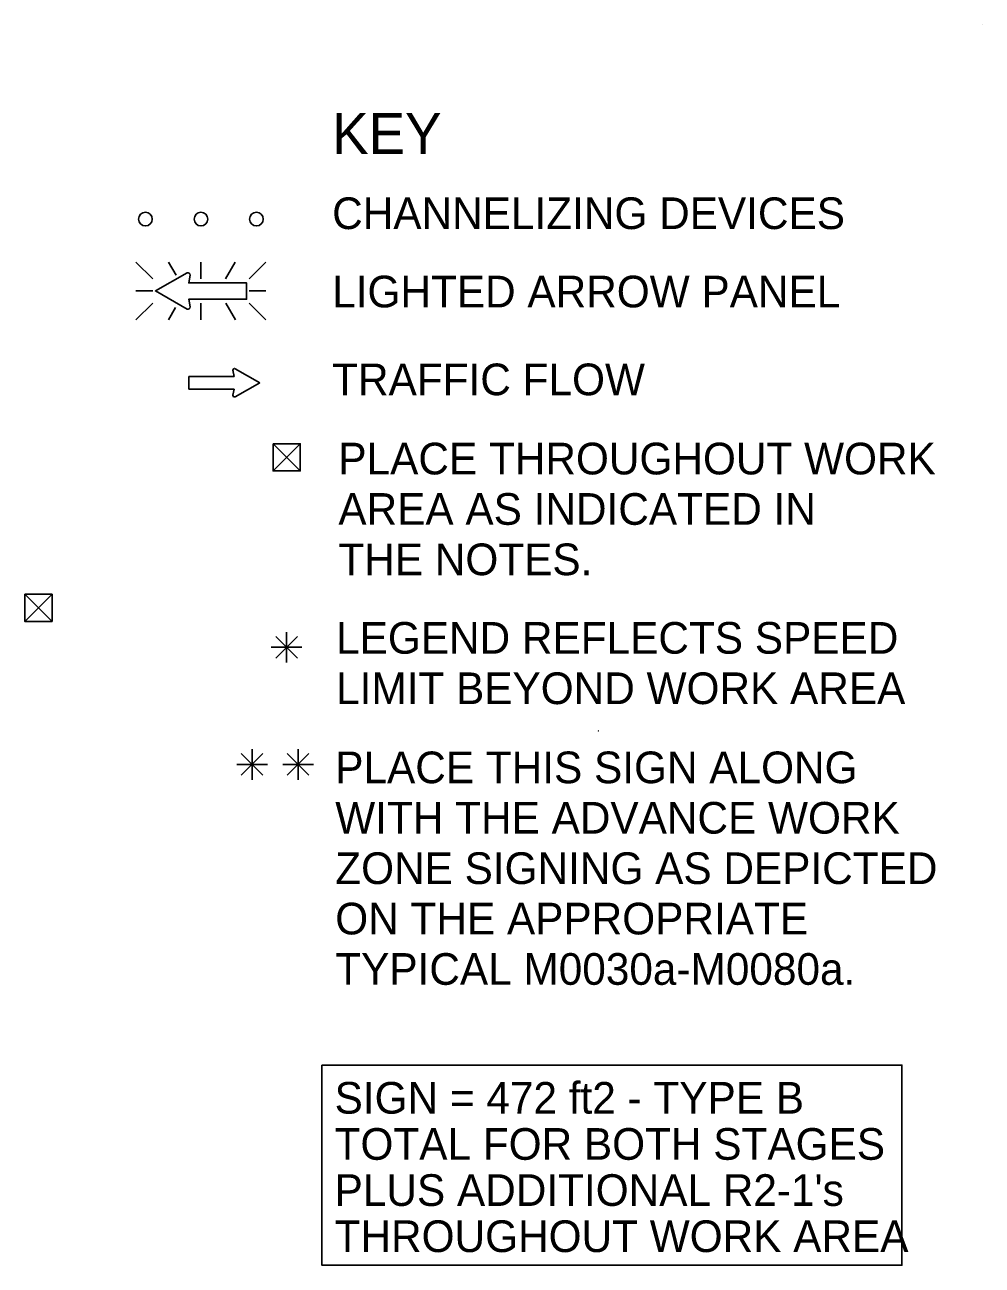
# Model space of a CAD drawing. Extents: x 16590 to 19508, y 5703 to 6974.
# Drawn here: x 17142.3 to 17423.5, y 6566.5 to 6930.8 of the extents above; entities that cross this region are included whole.
import ezdxf

# ---------------------------------------------------------------- set-up
doc = ezdxf.new("R2010")
doc.units = 0
for name, color, linetype in [('BORDER', 7, 'Continuous'), ('MT_SCRATCH_LEVEL_E', 7, 'Continuous'), ('TRAFFIC_SIGNS_PR', 7, 'Continuous'), ('TYPICAL_TEXT_DIMEN_EX', 7, 'Continuous'), ('TYPICAL_TEXT_DIMEN_PR', 7, 'Continuous')]:
    doc.layers.add(name, color=color, linetype=linetype)

msp = doc.modelspace()

# ---------------------------------------------------------------- linework, layer by layer
at = {"layer": 'BORDER'}
msp.add_line((17423.55, 6930.8), (17423.55, 6930.8), dxfattribs=at)
at = {"layer": 'MT_SCRATCH_LEVEL_E'}
for p, q in [((17203.77, 6827.55), (17190.52, 6827.55)), ((17190.52, 6827.55), (17190.52, 6823.81)), ((17203.46, 6829.33), (17203.77, 6827.55)), ((17211.38, 6825.7), (17204.14, 6829.81)), ((17190.52, 6823.81), (17203.77, 6823.81)), ((17203.77, 6823.81), (17203.46, 6822.03)), ((17204.14, 6821.55), (17211.38, 6825.7))]:
    msp.add_line(p, q, dxfattribs=at)
for centre, start, end in [((17203.92, 6829.4), 60.4248, 189.9638), ((17203.92, 6821.96), 170.0362, 299.7731)]:
    msp.add_arc(centre, 0.463, start, end, dxfattribs=at)
at = {"layer": 'TRAFFIC_SIGNS_PR'}
for p, q in [((17174.97, 6861.12), (17179.9, 6856.19)), ((17186.73, 6857.31), (17184.52, 6861.13)), ((17194.05, 6856.19), (17194.05, 6861.13)), ((17201.29, 6856.19), (17204.14, 6861.13)), ((17208.2, 6856.19), (17213.14, 6861.13)), ((17179.9, 6852.64), (17174.97, 6852.64)), ((17208.2, 6852.64), (17213.14, 6852.64)), ((17174.97, 6844.15), (17179.9, 6849.08)), ((17194.05, 6849.08), (17194.05, 6844.15)), ((17204.18, 6844.15), (17201.33, 6849.08)), ((17208.2, 6849.08), (17213.14, 6844.15)), ((17184.48, 6844.15), (17186.59, 6847.81))]:
    msp.add_line(p, q, dxfattribs=at)
for points in [[(17189.98, 6857.91), (17180.69, 6852.64), (17189.98, 6847.32)], [(17190.85, 6847.94), (17190.45, 6850.21), (17207.47, 6850.21), (17207.47, 6855.01), (17190.45, 6855.01), (17190.86, 6857.3)]]:
    msp.add_lwpolyline(points, dxfattribs=at)
for centre in [(17177.76, 6873.75), (17194.06, 6873.75), (17210.36, 6873.75)]:
    msp.add_circle(centre, 2, dxfattribs=at)
for centre, radius, start, end in [((17190.27, 6857.39), 0.598, 350.7308, 118.8916), ((17190.26, 6847.84), 0.597, 241.4833, 9.9593)]:
    msp.add_arc(centre, radius, start, end, dxfattribs=at)
at = {"layer": 'TYPICAL_TEXT_DIMEN_EX'}
msp.add_lwpolyline([(17229.59, 6625.26), (17399.96, 6625.26), (17399.96, 6566.51), (17229.59, 6566.51)], close=True, dxfattribs=at)
at = {"layer": 'TYPICAL_TEXT_DIMEN_PR'}
for p, q in [((17215.24, 6807.77), (17223.24, 6799.77)), ((17215.24, 6799.77), (17223.24, 6807.77)), ((17142.31, 6763.56), (17150.31, 6755.56)), ((17142.31, 6755.56), (17150.31, 6763.56)), ((17216.01, 6751.19), (17222.39, 6744.81)), ((17222.39, 6751.19), (17216.01, 6744.81)), ((17219.2, 6748), (17219.2, 6752.46)), ((17219.2, 6748), (17214.67, 6748)), ((17219.2, 6748), (17222.39, 6748)), ((17219.2, 6748), (17223.67, 6748)), ((17219.2, 6748), (17219.2, 6743.5)), ((17209.1, 6713.6), (17209.1, 6718.06)), ((17222.6, 6713.6), (17222.6, 6718.06)), ((17205.91, 6716.79), (17212.28, 6710.41)), ((17212.28, 6716.79), (17205.91, 6710.41)), ((17225.79, 6716.79), (17219.41, 6710.41)), ((17219.42, 6716.79), (17225.79, 6710.41)), ((17209.1, 6713.6), (17204.56, 6713.6)), ((17209.1, 6713.6), (17212.28, 6713.6)), ((17209.1, 6713.6), (17213.57, 6713.6)), ((17209.1, 6713.6), (17209.1, 6709.1)), ((17222.6, 6713.6), (17218.07, 6713.6)), ((17222.6, 6713.6), (17225.79, 6713.6)), ((17222.6, 6713.6), (17227.08, 6713.6)), ((17222.6, 6713.6), (17222.6, 6709.1))]:
    msp.add_line(p, q, dxfattribs=at)
for points in [[(17215.24, 6807.77), (17215.24, 6799.77), (17223.24, 6799.77), (17223.24, 6807.77)], [(17142.31, 6763.56), (17142.31, 6755.56), (17150.31, 6755.56), (17150.31, 6763.56)]]:
    msp.add_lwpolyline(points, close=True, dxfattribs=at)
msp.add_open_spline([(17310.78, 6723.42), (17310.81, 6723.42), (17310.81, 6723.42), (17310.81, 6723.42)], degree=2, dxfattribs=at)

# ---------------------------------------------------------------- texts
at = {"layer": 'TYPICAL_TEXT_DIMEN_EX'}
for s, height, p in [('KEY', 12, (17232.6, 6892.86)), ('CHANNELIZING DEVICES', 9.3, (17232.6, 6870.81)), ('LIGHTED ARROW PANEL', 9.3, (17232.6, 6847.81)), ('TRAFFIC FLOW', 9.3, (17232.6, 6822.01)), ('PLACE THROUGHOUT WORK', 9.3, (17234.42, 6798.76)), ('AREA AS INDICATED IN', 9.3, (17234.42, 6783.96)), ('THE NOTES.', 9.3, (17234.42, 6769.16)), ('LEGEND REFLECTS SPEED', 9.3, (17233.75, 6746.1)), ('LIMIT BEYOND WORK AREA', 9.3, (17233.75, 6731.3)), ('PLACE THIS SIGN ALONG', 9.3, (17233.51, 6708.06)), ('WITH THE ADVANCE WORK', 9.3, (17233.51, 6693.26)), ('ZONE SIGNING AS DEPICTED', 9.3, (17233.51, 6678.46)), ('ON THE APPROPRIATE', 9.3, (17233.51, 6663.66)), ('TYPICAL M0030a-M0080a.', 9.3, (17233.51, 6648.86)), ('SIGN = 472 ft2 - TYPE B', 9.3, (17233.32, 6611.02)), ('TOTAL FOR BOTH STAGES', 9.3, (17233.32, 6597.47)), ("PLUS ADDITIONAL R2-1's", 9.3, (17233.32, 6583.92)), ('THROUGHOUT WORK AREA', 9.3, (17233.32, 6570.37))]:
    msp.add_text(s, height=height, dxfattribs=at).set_placement(p)

doc.saveas('drawing.dxf')
